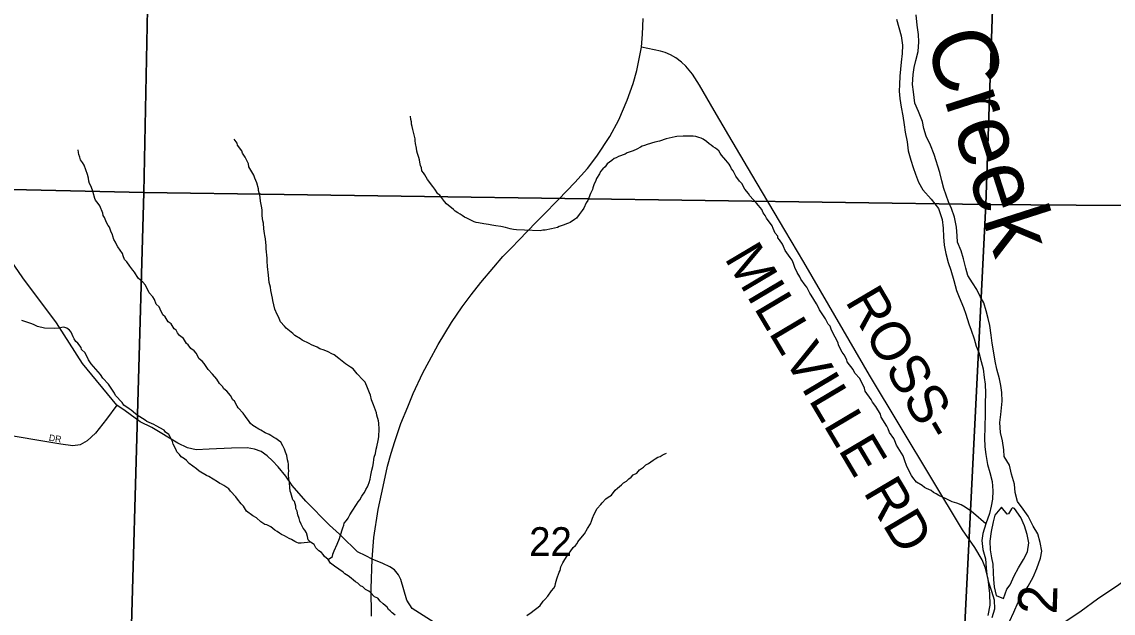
# Model space of a CAD drawing. Extents: x 1310247 to 1552180, y 377264 to 706493.
# Drawn here: x 1359384 to 1367792, y 494656 to 499210 of the extents above; entities that cross this region are included whole.
import ezdxf

# ---------------------------------------------------------------- set-up
doc = ezdxf.new("R2010")
doc.units = 0
for name, color, linetype in [('GM_X_Major_River', 7, 'Continuous'), ('GM_X_Major_River_Text', 7, 'Continuous'), ('GM_X_Minor_River', 7, 'Continuous'), ('GM_X_Section', 7, 'Continuous'), ('GM_X_Section_Text', 7, 'Continuous'), ('GM_X_State_Route', 7, 'Continuous'), ('GM_X_Township_Road', 7, 'Continuous'), ('GM_X_Township_Road_Text', 7, 'Continuous'), ('GM_X_Township_Subdivision', 7, 'Continuous'), ('GM_X_Township_Subdivision_Text', 7, 'Continuous'), ('GM_X_US_Route', 7, 'Continuous')]:
    doc.layers.add(name, color=color, linetype=linetype)

msp = doc.modelspace()

# ---------------------------------------------------------------- linework, layer by layer
at = {"layer": 'GM_X_Major_River'}
for points in [[(1366123.8, 499231.1), (1366141.9, 499166.3), (1366158.1, 499103.6), (1366168, 499031), (1366166.1, 498966.8), (1366158.1, 498898.8), (1366154.5, 498844.7), (1366149, 498792.7), (1366145, 498726.5), (1366143.5, 498676.4), (1366147.9, 498620), (1366158, 498553.5), (1366172, 498486.8), (1366182.1, 498418.2), (1366190.4, 498359.8), (1366204.3, 498287.1), (1366212.2, 498216.6), (1366232.2, 498143.7), (1366250.6, 498089), (1366269.2, 498038.2), (1366293.4, 497975.3), (1366325.8, 497916.1), (1366389.8, 497844), (1366445.9, 497772), (1366473.6, 497688.9), (1366483.6, 497620.3), (1366485.6, 497554), (1366489.8, 497489.7), (1366504, 497427), (1366521.9, 497356.2), (1366540.3, 497297.4), (1366564, 497218.5), (1366585.8, 497141.5), (1366604.4, 497090.8), (1366638.1, 497009.5), (1366656.7, 496958.7), (1366680.6, 496885.7), (1366699.2, 496835), (1366721.4, 496770.1), (1366737.7, 496713.4), (1366756.3, 496662.7), (1366776.3, 496593.8), (1366790.7, 496537.2), (1366798.8, 496470.7), (1366805.3, 496420.3), (1366807.3, 496350), (1366805, 496271.7), (1366806.7, 496195.4), (1366803.4, 496083), (1366801.2, 496006.8), (1366803.2, 495938.5), (1366811.4, 495878), (1366825.2, 495801.3), (1366841.4, 495738.6), (1366859.5, 495669.8), (1366865.4, 495599.4), (1366861.5, 495535.2), (1366851.9, 495479.3), (1366838.2, 495423.5), (1366811.7, 495343.9), (1366787.5, 495270.4), (1366779.9, 495216.4), (1366787.8, 495145.9), (1366807.8, 495075), (1366813.8, 495004.6), (1366818.3, 494952.2), (1366828.8, 494901.7), (1366854.7, 494826.7), (1366874.7, 494757.8)], [(1366992.2, 494591.7), (1367026.4, 494663), (1367060.9, 494742.3), (1367092.5, 494793.6), (1367136.7, 494864.6), (1367174.9, 494933.7), (1367202.9, 494999.2), (1367233.3, 495078.6), (1367243, 495134.5), (1367230.9, 495201.1), (1367210.8, 495268), (1367176.4, 495327.2), (1367136.5, 495402.7), (1367098, 495456), (1367055.6, 495517.5), (1367037.5, 495584.3), (1367031.4, 495648.7), (1367007.6, 495727.7), (1366993.6, 495796.4), (1366953.5, 495863.8), (1366948.9, 495914.1), (1366938.9, 495982.7), (1366924.8, 496047.4), (1366919, 496123.8), (1366926.8, 496185.8), (1366932.4, 496237.9), (1366935.9, 496288), (1366933.9, 496356.3), (1366925.5, 496410.8), (1366916.9, 496461.2), (1366895, 496536.1), (1366882.8, 496596.7), (1366869, 496675.4), (1366858.8, 496736), (1366852.5, 496796.4), (1366840.7, 496871), (1366830.3, 496925.5), (1366813.9, 496984.2), (1366795.7, 497045), (1366767.1, 497096), (1366742.6, 497149), (1366708, 497200.2), (1366673.5, 497257.4), (1366657.1, 497312.1), (1366639.2, 497384.9), (1366620.9, 497447.7), (1366592.8, 497512.7), (1366590.2, 497563), (1366586.2, 497629.4), (1366570.4, 497706.1), (1366546.3, 497773.1), (1366523.7, 497824), (1366505.1, 497874.7), (1366488.6, 497925.4), (1366472.3, 497986.1), (1366456.1, 498050.8), (1366412, 498188.6), (1366386, 498259.7), (1366352, 498328.9), (1366333.6, 498387.7), (1366323.2, 498442.2), (1366293.4, 498519.4), (1366265.2, 498584.5), (1366253.7, 498671.1), (1366247.4, 498727.5), (1366251.7, 498805.7), (1366259.3, 498859.7), (1366272.8, 498911.5), (1366288.9, 498981.3), (1366295.2, 499057.4), (1366292.8, 499113.7), (1366280.9, 499184.3), (1366273.2, 499264.8)], [(1366974.5, 495419.5), (1366931.9, 495472.9), (1366880, 495412.2), (1366868.4, 495360.3), (1366852.1, 495284.5), (1366841.9, 495210.5), (1366844, 495144.2), (1366854.2, 495083.7), (1366864.8, 495033.2), (1366866.8, 494966.9), (1366869.3, 494914.6), (1366875.7, 494858.2), (1366891.8, 494793.5), (1366947.3, 494769.8), (1366973.5, 494841.3)], [(1366973.5, 494841.3), (1366998.6, 494874.7), (1367030.7, 494944), (1367062.6, 495005.3), (1367100.6, 495070.4), (1367132.5, 495129.7), (1367142.5, 495197.7), (1367130.4, 495262.3), (1367110.3, 495329.2), (1367080.1, 495394.3), (1367031.9, 495462)], [(1367031.9, 495462), (1367015.5, 495467.6), (1367009, 495459.8), (1366984.6, 495421.3), (1366974.5, 495419.5)], [(1366874.7, 494757.8), (1366876.7, 494687.5), (1366858.6, 494619.8)]]:
    msp.add_lwpolyline(points, dxfattribs=at)
at = {"layer": 'GM_X_Minor_River'}
for points in [[(1362395.8, 498380.7), (1362392.5, 498404.8), (1362387, 498423), (1362385.5, 498441.1), (1362382, 498457.3), (1362378.7, 498483.5)], [(1364659, 498288.8), (1364633.4, 498305.6), (1364617.5, 498314.1), (1364599.7, 498320.7), (1364575.8, 498327.4), (1364555.8, 498330), (1364533.7, 498330.7), (1364513.6, 498329.3), (1364479.5, 498330.3), (1364431.3, 498327.7), (1364417.1, 498324.1), (1364348.5, 498310.1), (1364297.8, 498291.6), (1364261.4, 498282.7), (1364202.7, 498264.4), (1364182.4, 498259), (1364164.2, 498251.5), (1364149.9, 498245.9), (1364123.4, 498230.6), (1364092.9, 498215.5), (1364048.3, 498200.8), (1364031.9, 498191.3), (1363981.2, 498172.7), (1363962.9, 498163.2), (1363948.7, 498157.7), (1363930.2, 498142.2), (1363893.3, 498117.2), (1363878.6, 498093.6), (1363860.1, 498078.1), (1363843.4, 498056.5), (1363834.9, 498040.7), (1363811.7, 498003.3), (1363805.3, 497989.5), (1363790.2, 497953.8), (1363783.5, 497932), (1363781.1, 497918), (1363764.2, 497888.4), (1363753.2, 497854.6), (1363744.6, 497834.9), (1363732, 497817.2), (1363714.8, 497775.6), (1363700.2, 497758), (1363677.2, 497726.6), (1363656.3, 497699.1), (1363642, 497687.5), (1363609.2, 497664.4), (1363594.9, 497658.8), (1363580.8, 497655.2), (1363562.5, 497645.8), (1363524, 497634.9), (1363509.7, 497627.3), (1363465.3, 497616.6), (1363416.8, 497606), (1363396.7, 497604.6), (1363376.5, 497601.2), (1363256.2, 497604.8), (1363196.1, 497608.6), (1363172.1, 497611.3), (1363146.2, 497616.1), (1363110.3, 497625.2), (1363074.4, 497634.3), (1363036.5, 497639.5), (1363004.5, 497644.4), (1362978.5, 497649.2), (1362942.6, 497654.3), (1362902.7, 497663.5), (1362884.7, 497666.1), (1362868.8, 497670.5), (1362852.9, 497677), (1362833.1, 497687.7), (1362811.4, 497698.3), (1362793.6, 497706.9), (1362775.8, 497717.5), (1362760.1, 497728), (1362742.4, 497740.5), (1362722.6, 497751.1), (1362709, 497765.6), (1362656.1, 497809.3), (1362640.6, 497827.8), (1362617.3, 497856.6), (1362603.8, 497875), (1362588, 497885.5), (1362565, 497922.3), (1362551.5, 497940.8), (1362509, 497996.2), (1362487.9, 498030.9), (1362478.4, 498047.3), (1362466.8, 498063.6), (1362463.4, 498085.8), (1362455.9, 498104.1), (1362450.6, 498128.3), (1362447.2, 498148.5), (1362441.7, 498164.7), (1362432.5, 498195), (1362427.1, 498215.3), (1362425.7, 498237.4), (1362416.7, 498273.7), (1362415.3, 498293.8), (1362413.7, 498307.9), (1362401.2, 498360.4), (1362395.8, 498380.7)], [(1361206.4, 497924.9), (1361195.7, 497969.3), (1361178.7, 498006), (1361171.3, 498028.2), (1361133, 498093.6), (1361129.7, 498115.7), (1361105.1, 498168.6), (1361084, 498199.3), (1361078.5, 498217.5), (1361045.6, 498260.6), (1361042, 498274.8), (1361018.9, 498307.6)], [(1366811.7, 495343.9), (1366714.9, 495425.4), (1366697.3, 495442), (1366677.6, 495454.6), (1366652, 495471.4), (1366620.4, 495490.4), (1366586.7, 495503.5), (1366552.9, 495514.5), (1366525.1, 495525.4), (1366505.4, 495536), (1366450, 495563.7), (1366428.3, 495576.4), (1366408.4, 495585), (1366388.9, 495601.6), (1366355.2, 495616.7), (1366339.4, 495625.2), (1366321.7, 495639.8), (1366276.3, 495665.2), (1366249.2, 495700.1), (1366239.7, 495716.4), (1366201.6, 495785.8), (1366185, 495836.4), (1366173.9, 495868.8), (1366124.1, 495950.5), (1366109, 495983.1), (1366101.5, 496001.3), (1366068.7, 496048.5), (1366057.5, 496076.9), (1366048.1, 496097.2), (1366003.9, 496166.7), (1365998.6, 496188.9), (1365964.2, 496248.1), (1365937, 496281), (1365927.6, 496301.4), (1365881.3, 496365), (1365876, 496389.2), (1365840, 496462.5), (1365803.1, 496505.7), (1365789.8, 496532.1), (1365743.4, 496591.7), (1365739.8, 496607.8), (1365718.9, 496646.6), (1365703.4, 496667.1), (1365674.9, 496720.1), (1365673.4, 496738.2), (1365650.6, 496783), (1365635.3, 496809.5), (1365620.3, 496844.1), (1365610.9, 496866.4), (1365597.3, 496882.9), (1365576.5, 496923.6), (1365530.3, 496991.2), (1365520.8, 497009.5), (1365507.5, 497038), (1365465.3, 497105.4), (1365455.8, 497121.8), (1365433, 497166.6), (1365419.4, 497183), (1365386.6, 497228.1), (1365379.2, 497246.4), (1365358, 497279.1), (1365352.4, 497293.3), (1365340.9, 497311.7), (1365329.9, 497348.1), (1365318.7, 497374.6), (1365303.2, 497395.1), (1365264.7, 497450.4), (1365251.5, 497480.9), (1365244, 497497.1), (1365220.9, 497531.9), (1365209.3, 497546.3), (1365207.7, 497560.4), (1365188.3, 497583), (1365173.2, 497617.6), (1365163.8, 497639.9), (1365121.4, 497699.4), (1365109.9, 497717.8), (1365094.5, 497738.3), (1365085.2, 497764.6), (1365060, 497795.5), (1365044.5, 497814), (1365019.2, 497842.8), (1364993.9, 497869.6), (1364982.4, 497888), (1364955.3, 497920.9), (1364930.5, 497965.8), (1364913, 497984.4), (1364884, 498021.4), (1364865.1, 498062), (1364851.5, 498078.5), (1364840.1, 498100.9), (1364832.5, 498115.1), (1364807.3, 498146), (1364774.3, 498183.1), (1364764.7, 498199.4), (1364753.2, 498215.8), (1364727.7, 498236.6), (1364709.9, 498247.2), (1364696.2, 498259.6), (1364678.5, 498270.2), (1364659, 498288.8)], [(1361259.9, 496044), (1361224.4, 496065.1), (1361208.6, 496073.6), (1361177.1, 496092.6), (1361163.3, 496101.1), (1361145.7, 496117.6), (1361134.1, 496132), (1361107.1, 496171), (1361089.7, 496195.5), (1361050.8, 496236.8), (1361043.2, 496251.1), (1361022.2, 496287.8), (1361008.5, 496300.3), (1360991.4, 496332.9), (1360964.3, 496365.8), (1360940.7, 496384.5), (1360931.2, 496400.8), (1360905.8, 496425.7), (1360886.7, 496458.3), (1360851.7, 496497.5), (1360820.6, 496532.5), (1360787.9, 496579.6), (1360774.3, 496596.1), (1360750.8, 496614.8), (1360727.9, 496657.6), (1360712.4, 496676.1), (1360684.9, 496695), (1360665.6, 496721.7), (1360651.8, 496732.1), (1360628.9, 496770.9), (1360599.5, 496795.9), (1360584, 496814.4), (1360572.6, 496836.8), (1360556.8, 496845.3), (1360533.8, 496884.1), (1360510.2, 496900.8), (1360487.3, 496939.6), (1360469.6, 496954.2), (1360450.8, 496996.9), (1360441.3, 497015.2), (1360419.8, 497035.9), (1360404.9, 497072.5), (1360393.4, 497092.8), (1360364.2, 497123.8), (1360335.8, 497182.8), (1360316.4, 497205.5), (1360281.2, 497236.6), (1360252.4, 497281.6), (1360238.8, 497298), (1360215.7, 497328.8), (1360192.5, 497361.6), (1360175, 497380.2), (1360165.8, 497408.5), (1360158.3, 497426.8), (1360123.7, 497478), (1360110.3, 497500.4), (1360106.7, 497514.6), (1360093.2, 497535), (1360083.9, 497559.4), (1360082.3, 497573.5), (1360072.7, 497589.8), (1360059.8, 497628.3), (1360048.2, 497642.7), (1360036.8, 497665.1), (1360021.9, 497703.6), (1360010.3, 497718), (1360006.8, 497736.2), (1359984.3, 497793), (1359970.8, 497811.5), (1359951.5, 497836.1), (1359945.9, 497850.3), (1359933.1, 497894.8), (1359927.6, 497913), (1359914.6, 497947.5), (1359905.1, 497965.9), (1359899.6, 497984.1), (1359898.2, 498006.2), (1359889, 498034.5), (1359863, 498105.5), (1359851.6, 498127.9), (1359836.1, 498146.4), (1359830.7, 498168.7), (1359823.3, 498188.9), (1359821.7, 498205), (1359818.3, 498225.2)], [(1361745.3, 495068.8), (1361778.1, 495093.9), (1361780.7, 495111.9), (1361789.4, 495135.7), (1361813, 495187.1), (1361832.3, 495230.6), (1361836.8, 495248.6), (1361856.8, 495314.1), (1361865.4, 495334), (1361867.9, 495349.9), (1361884.5, 495369.5), (1361897.1, 495387.2), (1361911.9, 495414.8), (1361928.8, 495442.4), (1361962.4, 495493.5), (1361975, 495513.2), (1361987.5, 495528.9), (1362004.4, 495556.4), (1362014.8, 495572.2), (1362023.3, 495586), (1362034, 495609.7), (1362046.6, 495629.4), (1362051, 495643.3), (1362059.6, 495663.1), (1362066.4, 495689), (1362073.3, 495718.8), (1362080.5, 495758.7), (1362087.3, 495786.6), (1362092.1, 495814.5), (1362096.9, 495840.5), (1362099.5, 495858.4), (1362108.3, 495886.2), (1362113.2, 495918.2), (1362119.8, 495938.1), (1362129.3, 495985.9), (1362131.7, 495999.9), (1362134.2, 496017.8), (1362134.6, 496031.9), (1362137.4, 496057.9), (1362135.8, 496074), (1362135.2, 496120.1), (1362131.6, 496136.3), (1362118.9, 496180.8), (1362115.4, 496198.9), (1362093.1, 496259.8), (1362078.2, 496298.3), (1362071.2, 496334.6), (1362063.7, 496352.9), (1362046.8, 496391.5), (1362029.9, 496434.1), (1362012.4, 496452.7), (1361967.6, 496498.2), (1361936.6, 496537.2), (1361916.9, 496549.8), (1361877.6, 496577.1), (1361852.1, 496597.9), (1361826.6, 496618.7), (1361791.3, 496645.8), (1361773.5, 496654.4), (1361743.8, 496669.3), (1361712, 496682.3), (1361680.2, 496691.3), (1361660.5, 496703.9), (1361614.9, 496723.3), (1361597.1, 496733.9), (1361543.7, 496759.6), (1361529.9, 496768), (1361486.6, 496795.4), (1361470.9, 496809.9), (1361419.9, 496851.5), (1361408.3, 496865.9), (1361377.2, 496898.9), (1361360.3, 496939.5), (1361350.7, 496955.9), (1361333.9, 496998.5), (1361317.8, 497065.2), (1361314.3, 497081.3), (1361302, 497141.8), (1361300.7, 497166), (1361289.7, 497202.4), (1361283.3, 497258.7), (1361277.3, 497327.1), (1361274.4, 497367.3), (1361273.1, 497391.4), (1361267.2, 497461.8), (1361265.8, 497483.9), (1361261.4, 497538.2), (1361256.1, 497564.4), (1361254.6, 497580.5), (1361247.6, 497616.8), (1361244.8, 497659), (1361241.3, 497677.2), (1361236.4, 497715.4), (1361235.3, 497745.5), (1361235.8, 497761.6), (1361230.6, 497791.8), (1361223.7, 497830.1), (1361220.5, 497858.3), (1361217, 497874.5), (1361208, 497910.8), (1361206.4, 497924.9)], [(1361608.7, 495203.2), (1361536.2, 495195.4), (1361516.2, 495196), (1361502.3, 495200.4), (1361486.5, 495208.9), (1361462.8, 495223.7), (1361443, 495232.3), (1361425.2, 495242.8), (1361407.4, 495251.4), (1361385.7, 495262.1), (1361369.9, 495272.6), (1361350.2, 495285.2), (1361332.4, 495295.8), (1361301.1, 495320.8), (1361271.4, 495335.7), (1361255.5, 495340.2), (1361225.9, 495359.1), (1361190.7, 495390.3), (1361163.1, 495407.1), (1361116, 495442.6), (1361091, 495481.5), (1361073.4, 495498.1), (1361044.4, 495535), (1361032.9, 495553.4), (1360992, 495596.8), (1360978.5, 495613.2), (1360939, 495638.5), (1360923.3, 495649), (1360909.4, 495655.4), (1360891.7, 495668), (1360858.2, 495687), (1360824.7, 495708.1), (1360806.9, 495716.6), (1360749.6, 495750.4), (1360730.1, 495769.1), (1360673.1, 495808.9), (1360651.7, 495831.6), (1360636, 495844.1), (1360612.4, 495860.8), (1360598.9, 495879.3), (1360579.3, 495897.9), (1360573.8, 495914.1), (1360549, 495959), (1360545.5, 495977.2), (1360526.5, 496013.8), (1360517, 496032.2), (1360491.5, 496051), (1360479.9, 496065.4), (1360418.6, 496099.3), (1360400.9, 496109.9), (1360347.4, 496133.5), (1360333.6, 496142), (1360313.9, 496154.6), (1360272.5, 496179.9), (1360258.7, 496190.3), (1360225.4, 496219.4), (1360209.7, 496229.9), (1360170.4, 496259.2), (1360156.9, 496277.6), (1360104.3, 496331.3), (1360096.8, 496351.6), (1360052.7, 496421.1), (1360007.9, 496466.6), (1359990.6, 496495.2), (1359918.8, 496577.6), (1359897.6, 496608.3), (1359873.1, 496661.2), (1359843.7, 496688.1), (1359840.1, 496702.3), (1359815, 496735.1), (1359799.4, 496749.6), (1359785.9, 496768.1), (1359778.3, 496784.3), (1359763.3, 496820.9), (1359751.7, 496835.3), (1359730.1, 496852), (1359708.2, 496858.6), (1359692.1, 496857.1), (1359669.9, 496851.8), (1359633.7, 496848.8), (1359557.5, 496851.1), (1359505.7, 496864.7), (1359478, 496877.6), (1359460.1, 496884.1), (1359382.6, 496910.5)], [(1362260.6, 494640.2), (1362237.1, 494659), (1362221.5, 494675.5), (1362207.7, 494683.9), (1362198.2, 494702.2), (1362168.8, 494727.2), (1362145.4, 494747.9), (1362126, 494772.6), (1362102.2, 494783.3), (1362071.1, 494816.3), (1362057.3, 494826.8), (1362031.6, 494839.6), (1362012.1, 494858.2), (1361994.3, 494866.8), (1361972.8, 494887.5), (1361955.1, 494898), (1361939.4, 494910.5), (1361921.7, 494925.1), (1361898.2, 494943.9), (1361872.5, 494958.7), (1361858.8, 494971.1), (1361827.5, 494996.1), (1361794, 495017.2), (1361762.6, 495042.2), (1361745.3, 495068.8), (1361715.9, 495093.7), (1361704.3, 495108.1), (1361692.7, 495124.5), (1361673, 495137.1), (1361649.6, 495159.9), (1361636.3, 495186.4), (1361608.7, 495203.2), (1361591.2, 495221.8), (1361585.9, 495248), (1361576.7, 495274.4), (1361563.2, 495294.9), (1361551.7, 495311.3), (1361536.5, 495341.8), (1361525.1, 495364.2), (1361519.7, 495384.4), (1361510.5, 495412.8), (1361505.3, 495443), (1361495.9, 495463.3), (1361494.4, 495481.4), (1361483.4, 495515.9), (1361471.7, 495530.3), (1361462.7, 495564.6), (1361457.2, 495582.8), (1361451.6, 495597), (1361448.4, 495625.2), (1361445.4, 495659.4), (1361443.9, 495677.5), (1361440.4, 495693.6), (1361439.1, 495717.8), (1361437.5, 495731.8), (1361440.1, 495751.8), (1361438.6, 495771.9), (1361437.6, 495804), (1361436, 495820.1), (1361430.6, 495838.4), (1361425.5, 495870.6), (1361416.1, 495894.9), (1361408.8, 495919.2), (1361395.5, 495943.7), (1361380.3, 495974.2), (1361362.6, 495986.8), (1361341, 496001.5), (1361325.2, 496010), (1361303.5, 496024.7), (1361289.7, 496031.1), (1361259.9, 496044)], [(1363274.1, 494637.9), (1363308.9, 494661), (1363331.5, 494680.3), (1363362.3, 494703.5), (1363376.7, 494715.1), (1363399.7, 494748.5), (1363414.2, 494762.1), (1363437, 494787.5), (1363464.3, 494828.8), (1363482.9, 494848.3), (1363493.5, 494868), (1363496, 494886), (1363507.1, 494921.8), (1363511.5, 494935.7), (1363518.1, 494955.5), (1363524.6, 494971.4), (1363531, 494985.2), (1363537.9, 495013.1), (1363552.8, 495042.8), (1363567.7, 495070.4), (1363586.5, 495097.9), (1363607.4, 495127.4), (1363630.5, 495160.8), (1363649, 495176.3), (1363663.5, 495191.9), (1363667.9, 495205.8), (1363690.8, 495233.2), (1363719.9, 495268.4), (1363743.2, 495307.8), (1363764.3, 495345.3), (1363772.9, 495365.1), (1363779.6, 495387), (1363792.5, 495418.6), (1363815.9, 495462.1), (1363844.9, 495493.3), (1363855.3, 495507), (1363884.3, 495536.2), (1363900.7, 495549.8), (1363927.3, 495565), (1363956.5, 495604.3), (1363973, 495619.8), (1364003.8, 495645), (1364018.3, 495660.6), (1364042.8, 495673.9), (1364059.4, 495691.5), (1364079.8, 495702.9), (1364094.4, 495720.5), (1364122.9, 495735.7), (1364143.7, 495761.1), (1364174.4, 495780.3), (1364190.9, 495797.8), (1364211.3, 495809.2), (1364229.7, 495820.7), (1364248.2, 495834.2), (1364264.5, 495843.8), (1364283, 495857.2), (1364301.2, 495862.7), (1364317.5, 495872.2), (1364331.8, 495879.8), (1364350.1, 495887.3)]]:
    msp.add_lwpolyline(points, dxfattribs=at)
at = {"layer": 'GM_X_Section'}
for points in [[(1360428.2, 503161.6), (1360324.4, 497895.4), (1355014.7, 498016.2), (1355120.9, 503300.4)], [(1366992.5, 503140.2), (1366811, 497804), (1360324.4, 497895.4), (1360428.2, 503161.6)], [(1360324.4, 497895.4), (1360178, 492768.2), (1354901.1, 492842.3), (1355014.7, 498016.2)], [(1366811, 497804), (1366551.3, 492625.6), (1360178, 492768.2), (1360324.4, 497895.4)]]:
    msp.add_lwpolyline(points, close=True, dxfattribs=at)
for points in [[(1370981.1, 497772.6), (1366811, 497804), (1366992.5, 503140.2), (1372373.2, 503099.2)], [(1371406.9, 492604.4), (1366551.3, 492625.6), (1366811, 497804), (1370981.1, 497772.6)]]:
    msp.add_lwpolyline(points, dxfattribs=at)
at = {"layer": 'GM_X_State_Route'}
msp.add_lwpolyline([(1366467.6, 493847.7), (1366504.8, 493884.3), (1366565.4, 493956.8), (1366653.9, 494036.9), (1366734.3, 494105.9), (1366895.5, 494224.2), (1367073, 494354.1), (1367240.2, 494472.2), (1367411.1, 494585.4), (1367544.7, 494675), (1367670.6, 494767.1), (1367834.6, 494876.8), (1368009.1, 495008.9), (1368147.1, 495099.7), (1368284, 495197.6), (1368405, 495287.8)], dxfattribs=at)
at = {"layer": 'GM_X_Township_Road'}
for points in [[(1360116.8, 496258.7), (1359852.5, 496580), (1359649.9, 496891.8), (1359392.2, 497239.3), (1359301.7, 497370.4), (1359263.6, 497475.1), (1359179.7, 497705.2), (1359038.5, 498114.9), (1358995, 498224.8), (1358938.3, 498308.7), (1358875.3, 498366.7), (1358751.5, 498456.6), (1358647.2, 498525.8), (1358571.8, 498622.4), (1358485.9, 498807.3), (1358284.9, 499172.9), (1358257.1, 499245), (1358244.3, 499331.2), (1358234, 499453.8), (1358214.1, 499535.7), (1358181.5, 499638.6)], [(1366828.1, 494638.2), (1366844.4, 494719.1), (1366841.9, 494808.5), (1366829.8, 494918.5), (1366808.3, 495001.9), (1366782.5, 495067.2), (1366725.8, 495161.8), (1366632.1, 495297.6), (1365914.2, 496488.3), (1365602.2, 497028.6), (1365408.7, 497360.5), (1365262.1, 497605.9), (1365009.4, 498034.5), (1364832.3, 498333.6), (1364717.5, 498527.5), (1364604.5, 498722.2), (1364552, 498808.2), (1364500.5, 498869.7), (1364467.3, 498900.6), (1364423.1, 498932.4), (1364382.2, 498956.1), (1364341, 498974.1), (1364303.6, 498984.9), (1364256.7, 498994.8), (1364157.2, 499014.9)], [(1361830.7, 495264), (1361754.6, 495333), (1361573.1, 495519.1), (1361466.9, 495640.1), (1361418.5, 495710.9), (1361359.9, 495784.4), (1361315.2, 495830), (1361274.3, 495868.2), (1361228.6, 495900.7), (1361176.5, 495920.3), (1361120.7, 495929.6), (1360998.8, 495927.7), (1360826.5, 495920.3), (1360727.9, 495913.8), (1360659, 495928.7), (1360586.4, 495965), (1360386.3, 496085), (1360296, 496128.8), (1360180.6, 496214.4), (1360116.8, 496258.7)], [(1362572.6, 494574.2), (1362560.6, 494583.7), (1362391.2, 494692.7), (1362349.3, 494757.7), (1362303.7, 494916), (1362285.1, 494952.3), (1362254.4, 494990.4), (1362218.1, 495012.8), (1362164.1, 495037.9), (1362084.1, 495071.4), (1362033.8, 495097.5), (1361969.6, 495129.1), (1361843.9, 495252), (1361830.7, 495264)]]:
    msp.add_lwpolyline(points, dxfattribs=at)
at = {"layer": 'GM_X_Township_Subdivision'}
msp.add_lwpolyline([(1360116.8, 496258.7), (1360035.4, 496151.1), (1359950.7, 496043.2), (1359888.3, 495984.5), (1359832.5, 495952.9), (1359775.7, 495945.4), (1359685.4, 495957.5), (1359176.3, 496043.2), (1358943.5, 496080.4), (1358745.3, 496109.2), (1358655.9, 496125.1), (1358542.4, 496140), (1358470.7, 496120.4), (1358398.1, 496069.2), (1358365.5, 496008.7), (1358332.9, 495886.8), (1358266.8, 495617.8), (1358212.9, 495437.2), (1358187.7, 495331.1), (1358160.5, 495238.6), (1358137.4, 495142.1), (1358105.9, 495058.1), (1358060.8, 495007.7), (1357944.3, 494954.2)], dxfattribs=at)
at = {"layer": 'GM_X_US_Route'}
msp.add_lwpolyline([(1362078.5, 494633.9), (1362075.7, 494846.2), (1362084.1, 495071.4), (1362096.9, 495238.1), (1362128.9, 495455.1), (1362167.4, 495631.7), (1362202.2, 495787.9), (1362228.8, 495887.6), (1362258.8, 495977.4), (1362304.8, 496116.5), (1362357.4, 496245), (1362399.2, 496347.3), (1362474.2, 496507.8), (1362521.5, 496598.2), (1362591.9, 496724.5), (1362694.8, 496895.2), (1362776.4, 497014.2), (1362846.8, 497107), (1362920.4, 497204), (1363020.1, 497322), (1363090.8, 497403.3), (1363159.2, 497472.7), (1363211.8, 497529.2), (1363347.6, 497667.3), (1363399.2, 497718.7), (1363518.6, 497841), (1363645.2, 497972.2), (1363741.9, 498080.7), (1363814.9, 498175.7), (1363914.9, 498328), (1363982.3, 498454.3), (1364047.4, 498607.9), (1364095.1, 498735.2), (1364121.7, 498835.8), (1364157.2, 499014.9), (1364165.6, 499115.5), (1364171.4, 499234.9)], dxfattribs=at)

# ---------------------------------------------------------------- texts
at = {"layer": 'GM_X_Major_River_Text'}
msp.add_text('Creek', height=499.96, rotation=287.79463, dxfattribs=at).set_placement((1366339.5, 499076.3))
at = {"layer": 'GM_X_Section_Text'}
msp.add_text('22', height=221, rotation=0.00001, dxfattribs=at).set_placement((1363292.9, 495097.3))
at = {"layer": 'GM_X_Township_Road_Text'}
for s, rotation, p in [('MILLVILLE RD', 300.71037, (1364792.5, 497391.3)), ('ROSS-', 300.55082, (1365723, 497058.9)), ('2', 88.11117, (1367356.7, 494644.6))]:
    msp.add_text(s, height=300, rotation=rotation, dxfattribs=at).set_placement(p)
at = {"layer": 'GM_X_Township_Subdivision_Text'}
msp.add_text('DR', height=50, rotation=351.02664, dxfattribs=at).set_placement((1359589.5, 495984.6))

doc.saveas('drawing.dxf')
